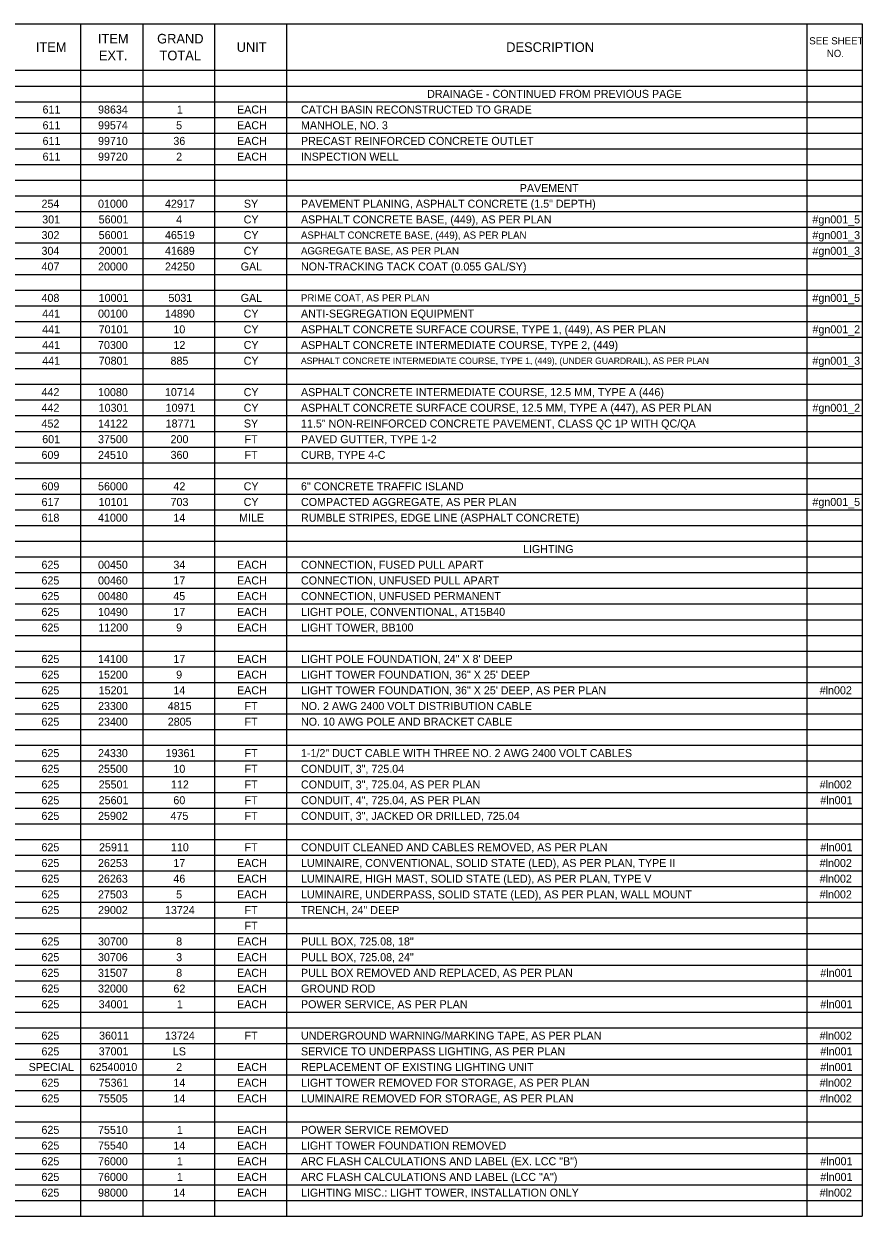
# Model space of a CAD drawing. Extents: x -542 to 295, y -281 to 32.
# Drawn here: x -525.86 to -511.19, y -70.44 to -49.59 of the extents above; entities that cross this region are included whole.
import ezdxf

# ---------------------------------------------------------------- set-up
doc = ezdxf.new("R2010")
doc.units = 0
doc.layers.add('SH_Data', color=7, linetype='Continuous')
doc.layers.add('SH_Text', color=7, linetype='Continuous')

msp = doc.modelspace()

# ---------------------------------------------------------------- linework, layer by layer
at = {"layer": 'SH_Data'}
for p, q in [((-541.706, -49.593), (-511.206, -49.593)), ((-524.87, -49.593), (-524.87, -70.444)), ((-523.785, -49.593), (-523.785, -70.444)), ((-522.529, -49.593), (-522.529, -70.444)), ((-521.273, -49.593), (-521.273, -70.444)), ((-512.174, -49.593), (-512.174, -70.444)), ((-511.206, -49.593), (-511.206, -70.444)), ((-541.706, -50.405), (-511.206, -50.405)), ((-541.706, -50.68), (-511.206, -50.68)), ((-541.706, -50.954), (-511.206, -50.954)), ((-541.706, -51.229), (-511.206, -51.229)), ((-541.706, -51.503), (-511.206, -51.503)), ((-541.706, -51.778), (-511.206, -51.778)), ((-541.706, -52.052), (-511.206, -52.052)), ((-541.706, -52.327), (-511.206, -52.327)), ((-541.706, -52.601), (-511.206, -52.601)), ((-541.706, -52.876), (-511.206, -52.876)), ((-541.706, -53.15), (-511.206, -53.15)), ((-541.706, -53.425), (-511.206, -53.425)), ((-541.706, -53.699), (-511.206, -53.699)), ((-541.706, -53.974), (-511.206, -53.974)), ((-541.706, -54.248), (-511.206, -54.248)), ((-541.706, -54.523), (-511.206, -54.523)), ((-541.706, -54.797), (-511.206, -54.797)), ((-541.706, -55.072), (-511.206, -55.072)), ((-541.706, -55.346), (-511.206, -55.346)), ((-541.706, -55.621), (-511.206, -55.621)), ((-541.706, -55.895), (-511.206, -55.895)), ((-541.706, -56.17), (-511.206, -56.17)), ((-541.706, -56.444), (-511.206, -56.444)), ((-541.706, -56.719), (-511.206, -56.719)), ((-541.706, -56.993), (-511.206, -56.993)), ((-541.706, -57.268), (-511.206, -57.268)), ((-541.706, -57.542), (-511.206, -57.542)), ((-541.706, -57.817), (-511.206, -57.817)), ((-541.706, -58.091), (-511.206, -58.091)), ((-541.706, -58.366), (-511.206, -58.366)), ((-541.706, -58.64), (-511.206, -58.64)), ((-541.706, -58.915), (-511.206, -58.915)), ((-541.706, -59.189), (-511.206, -59.189)), ((-541.706, -59.464), (-511.206, -59.464)), ((-541.706, -59.738), (-511.206, -59.738)), ((-541.706, -60.013), (-511.206, -60.013)), ((-541.706, -60.287), (-511.206, -60.287)), ((-541.706, -60.562), (-511.206, -60.562)), ((-541.706, -60.836), (-511.206, -60.836)), ((-541.706, -61.111), (-511.206, -61.111)), ((-541.706, -61.385), (-511.206, -61.385)), ((-541.706, -61.66), (-511.206, -61.66)), ((-541.706, -61.935), (-511.206, -61.935)), ((-541.706, -62.209), (-511.206, -62.209)), ((-541.706, -62.484), (-511.206, -62.484)), ((-541.706, -62.758), (-511.206, -62.758)), ((-541.706, -63.033), (-511.206, -63.033)), ((-541.706, -63.307), (-511.206, -63.307)), ((-541.706, -63.582), (-511.206, -63.582)), ((-541.706, -63.856), (-511.206, -63.856)), ((-541.706, -64.131), (-511.206, -64.131)), ((-541.706, -64.405), (-511.206, -64.405)), ((-541.706, -64.68), (-511.206, -64.68)), ((-541.706, -64.954), (-511.206, -64.954)), ((-541.706, -65.229), (-511.206, -65.229)), ((-541.706, -65.503), (-511.206, -65.503)), ((-541.706, -65.778), (-511.206, -65.778)), ((-541.706, -66.052), (-511.206, -66.052)), ((-541.706, -66.327), (-511.206, -66.327)), ((-541.706, -66.601), (-511.206, -66.601)), ((-541.706, -66.876), (-511.206, -66.876)), ((-541.706, -67.15), (-511.206, -67.15)), ((-541.706, -67.425), (-511.206, -67.425)), ((-541.706, -67.699), (-511.206, -67.699)), ((-541.706, -67.974), (-511.206, -67.974)), ((-541.706, -68.248), (-511.206, -68.248)), ((-541.706, -68.523), (-511.206, -68.523)), ((-541.706, -68.797), (-511.206, -68.797)), ((-541.706, -69.072), (-511.206, -69.072)), ((-541.706, -69.346), (-511.206, -69.346)), ((-541.706, -69.621), (-511.206, -69.621)), ((-541.706, -69.895), (-511.206, -69.895)), ((-541.706, -70.17), (-511.206, -70.17)), ((-541.706, -70.444), (-511.206, -70.444))]:
    msp.add_line(p, q, dxfattribs=at)

# ---------------------------------------------------------------- texts
at = {"layer": 'SH_Text'}
for s, height, p in [('ITEM', 0.168, (-524.569, -49.936)), ('GRAND ', 0.168, (-523.533, -49.936)), ('SEE SHEET ', 0.126, (-512.131, -49.952)), ('ITEM', 0.168, (-525.654, -50.083)), ('UNIT', 0.168, (-522.142, -50.083)), ('DESCRIPTION', 0.168, (-517.43, -50.083)), ('NO.', 0.126, (-511.824, -50.172)), ('EXT.', 0.168, (-524.552, -50.23)), ('TOTAL', 0.168, (-523.491, -50.23)), ('DRAINAGE - CONTINUED FROM PREVIOUS PAGE', 0.14, (-518.813, -50.887)), ('611', 0.14, (-525.536, -51.161)), ('98634', 0.14, (-524.566, -51.161)), ('1', 0.14, (-523.188, -51.161)), ('EACH', 0.14, (-522.136, -51.161)), ('CATCH BASIN RECONSTRUCTED TO GRADE', 0.14, (-521.018, -51.161)), ('611', 0.14, (-525.536, -51.436)), ('99574', 0.14, (-524.566, -51.436)), ('EACH', 0.14, (-522.136, -51.436)), ('MANHOLE, NO. 3', 0.14, (-521.018, -51.436)), ('5', 0.14, (-523.201, -51.436)), ('611', 0.14, (-525.536, -51.71)), ('99710', 0.14, (-524.566, -51.71)), ('36', 0.14, (-523.249, -51.71)), ('EACH', 0.14, (-522.136, -51.71)), ('PRECAST REINFORCED CONCRETE OUTLET', 0.14, (-521.018, -51.71)), ('611', 0.14, (-525.536, -51.985)), ('99720', 0.14, (-524.566, -51.985)), ('2', 0.14, (-523.2, -51.985)), ('EACH', 0.14, (-522.136, -51.985)), ('INSPECTION WELL', 0.14, (-521.018, -51.985)), ('PAVEMENT', 0.14, (-517.194, -52.534)), ('254', 0.14, (-525.554, -52.808)), ('01000', 0.14, (-524.566, -52.808)), ('42917', 0.14, (-523.396, -52.808)), ('SY', 0.14, (-522.016, -52.808)), ('PAVEMENT PLANING, ASPHALT CONCRETE (1.5" DEPTH)', 0.14, (-521.018, -52.808)), ('301', 0.14, (-525.542, -53.083)), ('56001', 0.14, (-524.555, -53.083)), ('4', 0.14, (-523.2, -53.083)), ('CY', 0.14, (-522.02, -53.083)), ('ASPHALT CONCRETE BASE, (449), AS PER PLAN', 0.14, (-521.018, -53.083)), ('#gn001_5', 0.14, (-512.076, -53.083)), ('302', 0.14, (-525.554, -53.357)), ('56001', 0.14, (-524.555, -53.357)), ('46519', 0.14, (-523.396, -53.357)), ('CY', 0.14, (-522.02, -53.357)), ('ASPHALT CONCRETE BASE, (449), AS PER PLAN', 0.126, (-521.018, -53.35)), ('#gn001_3', 0.14, (-512.076, -53.357)), ('304', 0.14, (-525.554, -53.632)), ('20001', 0.14, (-524.555, -53.632)), ('41689', 0.14, (-523.396, -53.632)), ('CY', 0.14, (-522.02, -53.632)), ('AGGREGATE BASE, AS PER PLAN', 0.126, (-521.018, -53.625)), ('#gn001_3', 0.14, (-512.076, -53.632)), ('407', 0.14, (-525.554, -53.906)), ('20000', 0.14, (-524.566, -53.906)), ('24250', 0.14, (-523.396, -53.906)), ('GAL', 0.14, (-522.072, -53.906)), ('NON-TRACKING TACK COAT (0.055 GAL/SY)', 0.14, (-521.018, -53.906)), ('408', 0.14, (-525.554, -54.455)), ('10001', 0.14, (-524.555, -54.455)), ('5031', 0.14, (-523.335, -54.455)), ('GAL', 0.14, (-522.072, -54.455)), ('PRIME COAT, AS PER PLAN', 0.126, (-521.018, -54.448)), ('#gn001_5', 0.14, (-512.076, -54.455)), ('441', 0.14, (-525.542, -54.73)), ('00100', 0.14, (-524.566, -54.73)), ('14890', 0.14, (-523.396, -54.73)), ('CY', 0.14, (-522.02, -54.73)), ('ANTI-SEGREGATION EQUIPMENT', 0.14, (-521.018, -54.73)), ('441', 0.14, (-525.542, -55.005)), ('70101', 0.14, (-524.555, -55.005)), ('10', 0.14, (-523.249, -55.005)), ('CY', 0.14, (-522.02, -55.005)), ('ASPHALT CONCRETE SURFACE COURSE, TYPE 1, (449), AS PER PLAN', 0.14, (-521.018, -55.005)), ('#gn001_2', 0.14, (-512.075, -55.005)), ('441', 0.14, (-525.542, -55.279)), ('70300', 0.14, (-524.566, -55.279)), ('12', 0.14, (-523.248, -55.279)), ('CY', 0.14, (-522.02, -55.279)), ('ASPHALT CONCRETE INTERMEDIATE COURSE, TYPE 2, (449)', 0.14, (-521.018, -55.279)), ('441', 0.14, (-525.542, -55.554)), ('70801', 0.14, (-524.555, -55.554)), ('885', 0.14, (-523.299, -55.554)), ('CY', 0.14, (-522.02, -55.554)), ('ASPHALT CONCRETE INTERMEDIATE COURSE, TYPE 1, (449), (UNDER GUARDRAIL), AS PER PLAN', 0.112, (-521.018, -55.54)), ('#gn001_3', 0.14, (-512.076, -55.554)), ('442', 0.14, (-525.554, -56.103)), ('10080', 0.14, (-524.566, -56.103)), ('10714', 0.14, (-523.396, -56.103)), ('CY', 0.14, (-522.02, -56.103)), ('ASPHALT CONCRETE INTERMEDIATE COURSE, 12.5 MM, TYPE A (446)', 0.14, (-521.018, -56.103)), ('442', 0.14, (-525.554, -56.377)), ('10301', 0.14, (-524.555, -56.377)), ('10971', 0.14, (-523.384, -56.377)), ('CY', 0.14, (-522.02, -56.377)), ('ASPHALT CONCRETE SURFACE COURSE, 12.5 MM, TYPE A (447), AS PER PLAN', 0.14, (-521.018, -56.377)), ('#gn001_2', 0.14, (-512.075, -56.377)), ('11.5" NON-REINFORCED CONCRETE PAVEMENT, CLASS QC 1P WITH QC/QA', 0.14, (-521.018, -56.652)), ('452', 0.14, (-525.554, -56.652)), ('14122', 0.14, (-524.566, -56.652)), ('18771', 0.14, (-523.384, -56.652)), ('SY', 0.14, (-522.016, -56.652)), ('601', 0.14, (-525.542, -56.926)), ('37500', 0.14, (-524.566, -56.926)), ('200', 0.14, (-523.298, -56.926)), ('FT', 0.14, (-522.005, -56.926)), ('PAVED GUTTER, TYPE 1-2', 0.14, (-521.018, -56.926)), ('609', 0.14, (-525.554, -57.201)), ('24510', 0.14, (-524.566, -57.201)), ('360', 0.14, (-523.298, -57.201)), ('FT', 0.14, (-522.005, -57.201)), ('CURB, TYPE 4-C', 0.14, (-521.018, -57.201)), ('609', 0.14, (-525.554, -57.75)), ('56000', 0.14, (-524.566, -57.75)), ('42', 0.14, (-523.248, -57.75)), ('CY', 0.14, (-522.02, -57.75)), ('6" CONCRETE TRAFFIC ISLAND', 0.14, (-521.018, -57.75)), ('617', 0.14, (-525.554, -58.024)), ('10101', 0.14, (-524.555, -58.024)), ('703', 0.14, (-523.298, -58.024)), ('CY', 0.14, (-522.02, -58.024)), ('COMPACTED AGGREGATE, AS PER PLAN', 0.14, (-521.018, -58.024)), ('#gn001_5', 0.14, (-512.076, -58.024)), ('618', 0.14, (-525.554, -58.299)), ('41000', 0.14, (-524.566, -58.299)), ('14', 0.14, (-523.249, -58.299)), ('MILE', 0.14, (-522.1, -58.299)), ('RUMBLE STRIPES, EDGE LINE (ASPHALT CONCRETE)', 0.14, (-521.018, -58.299)), ('LIGHTING', 0.14, (-517.136, -58.848)), ('625', 0.14, (-525.555, -59.122)), ('00450', 0.14, (-524.566, -59.122)), ('34', 0.14, (-523.249, -59.122)), ('EACH', 0.14, (-522.136, -59.122)), ('CONNECTION, FUSED PULL APART', 0.14, (-521.018, -59.122)), ('625', 0.14, (-525.555, -59.397)), ('00460', 0.14, (-524.566, -59.397)), ('17', 0.14, (-523.249, -59.397)), ('EACH', 0.14, (-522.136, -59.397)), ('CONNECTION, UNFUSED PULL APART', 0.14, (-521.018, -59.397)), ('625', 0.14, (-525.555, -59.671)), ('00480', 0.14, (-524.566, -59.671)), ('45', 0.14, (-523.25, -59.671)), ('EACH', 0.14, (-522.136, -59.671)), ('CONNECTION, UNFUSED PERMANENT', 0.14, (-521.018, -59.671)), ('625', 0.14, (-525.555, -59.946)), ('10490', 0.14, (-524.566, -59.946)), ('17', 0.14, (-523.249, -59.946)), ('EACH', 0.14, (-522.136, -59.946)), ('LIGHT POLE, CONVENTIONAL, AT15B40', 0.14, (-521.018, -59.946)), ('625', 0.14, (-525.555, -60.22)), ('11200', 0.14, (-524.56, -60.22)), ('9', 0.14, (-523.2, -60.22)), ('EACH', 0.14, (-522.136, -60.22)), ('LIGHT TOWER, BB100', 0.14, (-521.018, -60.22)), ('625', 0.14, (-525.555, -60.769)), ('14100', 0.14, (-524.566, -60.769)), ('17', 0.14, (-523.249, -60.769)), ('EACH', 0.14, (-522.136, -60.769)), ('LIGHT POLE FOUNDATION, 24" X 8\' DEEP', 0.14, (-521.018, -60.769)), ('625', 0.14, (-525.555, -61.044)), ('15200', 0.14, (-524.566, -61.044)), ('9', 0.14, (-523.2, -61.044)), ('EACH', 0.14, (-522.136, -61.044)), ('LIGHT TOWER FOUNDATION, 36" X 25\' DEEP', 0.14, (-521.018, -61.044)), ('625', 0.14, (-525.555, -61.318)), ('15201', 0.14, (-524.555, -61.318)), ('14', 0.14, (-523.249, -61.318)), ('EACH', 0.14, (-522.136, -61.318)), ('LIGHT TOWER FOUNDATION, 36" X 25\' DEEP, AS PER PLAN', 0.14, (-521.018, -61.318)), ('#ln002', 0.14, (-511.949, -61.318)), ('625', 0.14, (-525.555, -61.593)), ('23300', 0.14, (-524.566, -61.593)), ('4815', 0.14, (-523.347, -61.593)), ('FT', 0.14, (-522.005, -61.593)), ('NO. 2 AWG 2400 VOLT DISTRIBUTION CABLE', 0.14, (-521.018, -61.593)), ('625', 0.14, (-525.555, -61.867)), ('23400', 0.14, (-524.566, -61.867)), ('2805', 0.14, (-523.347, -61.867)), ('FT', 0.14, (-522.005, -61.867)), ('NO. 10 AWG POLE AND BRACKET CABLE', 0.14, (-521.018, -61.867)), ('625', 0.14, (-525.555, -62.416)), ('24330', 0.14, (-524.566, -62.416)), ('19361', 0.14, (-523.384, -62.416)), ('FT', 0.14, (-522.005, -62.416)), ('1-1/2" DUCT CABLE WITH THREE NO. 2 AWG 2400 VOLT CABLES', 0.14, (-521.018, -62.416)), ('625', 0.14, (-525.555, -62.691)), ('25500', 0.14, (-524.566, -62.691)), ('10', 0.14, (-523.249, -62.691)), ('FT', 0.14, (-522.005, -62.691)), ('CONDUIT, 3", 725.04', 0.14, (-521.018, -62.691)), ('625', 0.14, (-525.555, -62.965)), ('25501', 0.14, (-524.555, -62.965)), ('112', 0.14, (-523.291, -62.965)), ('FT', 0.14, (-522.005, -62.965)), ('CONDUIT, 3", 725.04, AS PER PLAN', 0.14, (-521.018, -62.965)), ('#ln002', 0.14, (-511.949, -62.965)), ('625', 0.14, (-525.555, -63.24)), ('25601', 0.14, (-524.555, -63.24)), ('60', 0.14, (-523.249, -63.24)), ('FT', 0.14, (-522.005, -63.24)), ('CONDUIT, 4", 725.04, AS PER PLAN', 0.14, (-521.018, -63.24)), ('#ln001', 0.14, (-511.938, -63.24)), ('625', 0.14, (-525.555, -63.514)), ('25902', 0.14, (-524.566, -63.514)), ('475', 0.14, (-523.299, -63.514)), ('FT', 0.14, (-522.005, -63.514)), ('CONDUIT, 3", JACKED OR DRILLED, 725.04', 0.14, (-521.018, -63.514)), ('625', 0.14, (-525.555, -64.063)), ('25911', 0.14, (-524.548, -64.063)), ('110', 0.14, (-523.292, -64.063)), ('FT', 0.14, (-522.005, -64.063)), ('CONDUIT CLEANED AND CABLES REMOVED, AS PER PLAN', 0.14, (-521.018, -64.063)), ('#ln001', 0.14, (-511.938, -64.063)), ('625', 0.14, (-525.555, -64.338)), ('26253', 0.14, (-524.567, -64.338)), ('17', 0.14, (-523.249, -64.338)), ('EACH', 0.14, (-522.136, -64.338)), ('LUMINAIRE, CONVENTIONAL, SOLID STATE (LED), AS PER PLAN, TYPE II', 0.14, (-521.018, -64.338)), ('#ln002', 0.14, (-511.949, -64.338)), ('625', 0.14, (-525.555, -64.612)), ('26263', 0.14, (-524.567, -64.612)), ('46', 0.14, (-523.249, -64.612)), ('EACH', 0.14, (-522.136, -64.612)), ('LUMINAIRE, HIGH MAST, SOLID STATE (LED), AS PER PLAN, TYPE V', 0.14, (-521.018, -64.612)), ('#ln002', 0.14, (-511.949, -64.612)), ('625', 0.14, (-525.555, -64.887)), ('27503', 0.14, (-524.567, -64.887)), ('5', 0.14, (-523.201, -64.887)), ('EACH', 0.14, (-522.136, -64.887)), ('LUMINAIRE, UNDERPASS, SOLID STATE (LED), AS PER PLAN, WALL MOUNT', 0.14, (-521.018, -64.887)), ('#ln002', 0.14, (-511.949, -64.887)), ('625', 0.14, (-525.555, -65.161)), ('29002', 0.14, (-524.566, -65.161)), ('13724', 0.14, (-523.396, -65.161)), ('FT', 0.14, (-522.005, -65.161)), ('TRENCH, 24" DEEP', 0.14, (-521.018, -65.161)), ('FT', 0.14, (-522.005, -65.436)), ('625', 0.14, (-525.555, -65.71)), ('30700', 0.14, (-524.566, -65.71)), ('8', 0.14, (-523.2, -65.71)), ('EACH', 0.14, (-522.136, -65.71)), ('PULL BOX, 725.08, 18"', 0.14, (-521.018, -65.71)), ('625', 0.14, (-525.555, -65.985)), ('30706', 0.14, (-524.567, -65.985)), ('3', 0.14, (-523.2, -65.985)), ('EACH', 0.14, (-522.136, -65.985)), ('PULL BOX, 725.08, 24"', 0.14, (-521.018, -65.985)), ('625', 0.14, (-525.555, -66.259)), ('31507', 0.14, (-524.567, -66.259)), ('8', 0.14, (-523.2, -66.259)), ('EACH', 0.14, (-522.136, -66.259)), ('PULL BOX REMOVED AND REPLACED, AS PER PLAN', 0.14, (-521.018, -66.259)), ('#ln001', 0.14, (-511.938, -66.259)), ('625', 0.14, (-525.555, -66.534)), ('32000', 0.14, (-524.566, -66.534)), ('62', 0.14, (-523.248, -66.534)), ('EACH', 0.14, (-522.136, -66.534)), ('GROUND ROD', 0.14, (-521.018, -66.534)), ('625', 0.14, (-525.555, -66.808)), ('34001', 0.14, (-524.555, -66.808)), ('1', 0.14, (-523.188, -66.808)), ('EACH', 0.14, (-522.136, -66.808)), ('POWER SERVICE, AS PER PLAN', 0.14, (-521.018, -66.808)), ('#ln001', 0.14, (-511.938, -66.808)), ('625', 0.14, (-525.555, -67.357)), ('36011', 0.14, (-524.548, -67.357)), ('13724', 0.14, (-523.396, -67.357)), ('FT', 0.14, (-522.005, -67.357)), ('UNDERGROUND WARNING/MARKING TAPE, AS PER PLAN', 0.14, (-521.018, -67.357)), ('#ln002', 0.14, (-511.949, -67.357)), ('625', 0.14, (-525.555, -67.632)), ('37001', 0.14, (-524.555, -67.632)), ('LS', 0.14, (-523.258, -67.632)), ('SERVICE TO UNDERPASS LIGHTING, AS PER PLAN', 0.14, (-521.018, -67.632)), ('#ln001', 0.14, (-511.938, -67.632)), ('SPECIAL', 0.14, (-525.779, -67.906)), ('62540010', 0.14, (-524.713, -67.906)), ('2', 0.14, (-523.2, -67.906)), ('EACH', 0.14, (-522.136, -67.906)), ('REPLACEMENT OF EXISTING LIGHTING UNIT', 0.14, (-521.018, -67.906)), ('#ln001', 0.14, (-511.938, -67.906)), ('625', 0.14, (-525.555, -68.181)), ('75361', 0.14, (-524.555, -68.181)), ('14', 0.14, (-523.249, -68.181)), ('EACH', 0.14, (-522.136, -68.181)), ('LIGHT TOWER REMOVED FOR STORAGE, AS PER PLAN', 0.14, (-521.018, -68.181)), ('#ln002', 0.14, (-511.949, -68.181)), ('625', 0.14, (-525.555, -68.456)), ('75505', 0.14, (-524.567, -68.456)), ('14', 0.14, (-523.249, -68.456)), ('EACH', 0.14, (-522.136, -68.456)), ('LUMINAIRE REMOVED FOR STORAGE, AS PER PLAN', 0.14, (-521.018, -68.456)), ('#ln002', 0.14, (-511.949, -68.456)), ('625', 0.14, (-525.555, -69.005)), ('75510', 0.14, (-524.566, -69.005)), ('1', 0.14, (-523.188, -69.005)), ('EACH', 0.14, (-522.136, -69.005)), ('POWER SERVICE REMOVED', 0.14, (-521.018, -69.005)), ('625', 0.14, (-525.555, -69.279)), ('75540', 0.14, (-524.566, -69.279)), ('14', 0.14, (-523.249, -69.279)), ('EACH', 0.14, (-522.136, -69.279)), ('LIGHT TOWER FOUNDATION REMOVED', 0.14, (-521.018, -69.279)), ('625', 0.14, (-525.555, -69.554)), ('76000', 0.14, (-524.566, -69.554)), ('1', 0.14, (-523.188, -69.554)), ('EACH', 0.14, (-522.136, -69.554)), ('ARC FLASH CALCULATIONS AND LABEL (EX. LCC "B")', 0.14, (-521.018, -69.554)), ('#ln001', 0.14, (-511.938, -69.554)), ('625', 0.14, (-525.555, -69.828)), ('76000', 0.14, (-524.566, -69.828)), ('1', 0.14, (-523.188, -69.828)), ('EACH', 0.14, (-522.136, -69.828)), ('ARC FLASH CALCULATIONS AND LABEL (LCC "A")', 0.14, (-521.018, -69.828)), ('#ln001', 0.14, (-511.938, -69.828)), ('625', 0.14, (-525.555, -70.103)), ('98000', 0.14, (-524.566, -70.103)), ('14', 0.14, (-523.249, -70.103)), ('EACH', 0.14, (-522.136, -70.103)), ('LIGHTING MISC.: LIGHT TOWER, INSTALLATION ONLY', 0.14, (-521.018, -70.103)), ('#ln002', 0.14, (-511.949, -70.103))]:
    msp.add_text(s, height=height, dxfattribs=at).set_placement(p)

doc.saveas('drawing.dxf')
